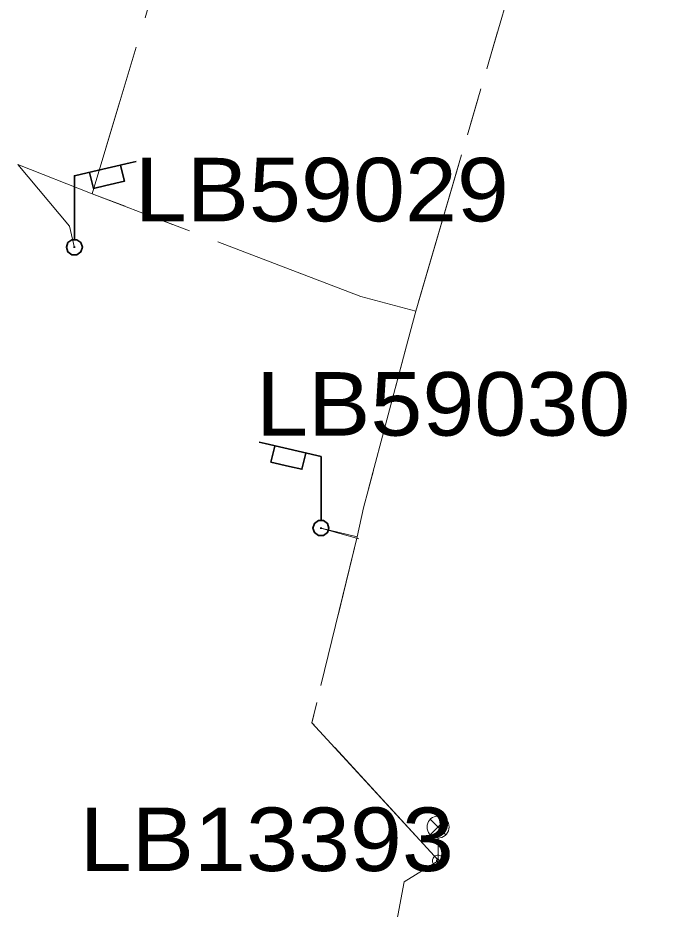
# Model space of a CAD drawing. Extents: x -688049 to -687261, y -973611 to -973038.
# Drawn here: x -687574.85 to -687553.08, y -973130.12 to -973099.72 of the extents above; entities that cross this region are included whole.
import ezdxf

# ---------------------------------------------------------------- set-up
doc = ezdxf.new("R2010")
doc.units = 0
doc.header["$LTSCALE"] = 0.87
doc.linetypes.add('LONG_DASH_SHORT_DASH', pattern=[9.9, 6, -1.2, 1.5, -1.2])
doc.layers.add('1', color=7, linetype='Continuous', lineweight=13)

msp = doc.modelspace()

# ---------------------------------------------------------------- linework, layer by layer
at = {"layer": '1', "linetype": 'LONG_DASH_SHORT_DASH'}
for p, q in [((-687561.28, -973109.72), (-687558.49, -973100.2)), ((-687561.28, -973109.72), (-687558.49, -973100.2)), ((-687571.38, -973102.61), (-687572.31, -973105.72)), ((-687571.38, -973102.61), (-687572.31, -973105.72)), ((-687571.38, -973102.61), (-687572.31, -973105.72)), ((-687572.31, -973105.72), (-687569.57, -973106.77)), ((-687572.31, -973105.72), (-687569.57, -973106.77)), ((-687572.31, -973105.72), (-687569.57, -973106.77)), ((-687564.51, -973117.12), (-687563.28, -973117.42)), ((-687564.51, -973117.12), (-687563.28, -973117.42)), ((-687564.51, -973117.12), (-687563.28, -973117.42)), ((-687564.51, -973117.12), (-687563.28, -973117.42)), ((-687564.51, -973117.12), (-687563.28, -973117.42)), ((-687564.51, -973117.12), (-687563.28, -973117.42)), ((-687564.51, -973117.12), (-687563.28, -973117.42)), ((-687564.51, -973117.12), (-687563.28, -973117.42)), ((-687563.93, -973120.09), (-687563.28, -973117.42)), ((-687563.93, -973120.09), (-687563.28, -973117.42)), ((-687563.93, -973120.09), (-687563.28, -973117.42)), ((-687563.93, -973120.09), (-687563.28, -973117.42))]:
    msp.add_line(p, q, dxfattribs=at)
at = {"layer": '1', "lineweight": 35}
for p, q in [((-687572.949, -973107.545), (-687572.895, -973107.545)), ((-687564.483, -973117.12), (-687564.537, -973117.12))]:
    msp.add_line(p, q, dxfattribs=at)
at = {"layer": '1'}
for p, q in [((-687563.22, -973117.487), (-687564.515, -973117.123)), ((-687560.785, -973127.055), (-687560.255, -973127.585)), ((-687560.785, -973127.585), (-687560.255, -973127.055)), ((-687560.52, -973128.47), (-687560.52, -973127.695))]:
    msp.add_line(p, q, dxfattribs=at)
at = {"layer": '1', "linetype": 'LONG_DASH_SHORT_DASH'}
for points in [[(-687572.31, -973105.72), (-687569.06, -973094.88), (-687566.56, -973083.47), (-687566.59, -973077.36), (-687568.45, -973067.24), (-687568.05, -973061.45)], [(-687572.31, -973105.72), (-687569.06, -973094.88), (-687566.56, -973083.47), (-687566.59, -973077.36), (-687568.45, -973067.24), (-687568.05, -973061.45)], [(-687572.31, -973105.72), (-687569.06, -973094.88), (-687566.56, -973083.47), (-687566.59, -973077.36), (-687568.45, -973067.24), (-687568.05, -973061.45)], [(-687572.31, -973105.72), (-687569.06, -973094.88), (-687566.56, -973083.47), (-687566.59, -973077.36), (-687568.45, -973067.24), (-687568.05, -973061.45)], [(-687553.08, -973087.49), (-687557.3, -973096.13), (-687561.28, -973109.72)], [(-687553.08, -973087.49), (-687557.3, -973096.13), (-687561.28, -973109.72)], [(-687553.08, -973087.49), (-687557.3, -973096.13), (-687561.28, -973109.72), (-687558.49, -973100.2)], [(-687553.08, -973087.49), (-687557.3, -973096.13), (-687561.28, -973109.72)], [(-687566.48, -973107.95), (-687563.15, -973109.23), (-687561.28, -973109.72), (-687558.49, -973100.2)], [(-687571.38, -973102.61), (-687572.31, -973105.72), (-687569.57, -973106.77)], [(-687572.31, -973105.72), (-687574.85, -973104.72), (-687573.09, -973106.82), (-687572.92, -973107.56)], [(-687572.92, -973107.56), (-687573.09, -973106.82), (-687574.85, -973104.72), (-687572.31, -973105.72)], [(-687572.92, -973107.56), (-687573.09, -973106.82), (-687574.85, -973104.72), (-687572.31, -973105.72)], [(-687572.31, -973105.72), (-687574.85, -973104.72), (-687573.09, -973106.82), (-687572.92, -973107.56)], [(-687572.92, -973107.56), (-687573.09, -973106.82), (-687574.85, -973104.72), (-687572.31, -973105.72)], [(-687572.31, -973105.72), (-687574.85, -973104.72), (-687573.09, -973106.82), (-687572.92, -973107.56)], [(-687572.31, -973105.72), (-687574.85, -973104.72), (-687573.09, -973106.82), (-687572.92, -973107.56)], [(-687572.92, -973107.56), (-687573.09, -973106.82), (-687574.85, -973104.72), (-687572.31, -973105.72)], [(-687561.28, -973109.72), (-687563.15, -973109.23), (-687572.31, -973105.72)], [(-687561.28, -973109.72), (-687563.15, -973109.23), (-687572.31, -973105.72)], [(-687561.28, -973109.72), (-687563.15, -973109.23), (-687572.31, -973105.72)], [(-687561.28, -973109.72), (-687563.15, -973109.23), (-687572.31, -973105.72)], [(-687566.48, -973107.95), (-687563.15, -973109.23), (-687561.28, -973109.72)], [(-687566.48, -973107.95), (-687563.15, -973109.23), (-687561.28, -973109.72)], [(-687566.48, -973107.95), (-687563.15, -973109.23), (-687561.28, -973109.72)], [(-687561.28, -973109.72), (-687561.55, -973110.74), (-687563.06, -973116.43), (-687563.28, -973117.42)], [(-687561.28, -973109.72), (-687561.55, -973110.74), (-687563.06, -973116.43), (-687563.28, -973117.42)], [(-687561.28, -973109.72), (-687561.55, -973110.74), (-687563.06, -973116.43), (-687563.28, -973117.42)], [(-687561.28, -973109.72), (-687561.55, -973110.74), (-687563.06, -973116.43), (-687563.28, -973117.42)], [(-687561.96, -973112.28), (-687561.55, -973110.74), (-687561.28, -973109.72)], [(-687561.96, -973112.28), (-687561.55, -973110.74), (-687561.28, -973109.72)], [(-687561.96, -973112.28), (-687561.55, -973110.74), (-687561.28, -973109.72)], [(-687561.96, -973112.28), (-687561.55, -973110.74), (-687561.28, -973109.72)], [(-687563.28, -973117.42), (-687563.06, -973116.43), (-687562.72, -973115.16)], [(-687563.28, -973117.42), (-687563.06, -973116.43), (-687562.72, -973115.16)], [(-687563.28, -973117.42), (-687563.06, -973116.43), (-687562.72, -973115.16)], [(-687563.28, -973117.42), (-687563.06, -973116.43), (-687562.72, -973115.16)], [(-687563.28, -973117.42), (-687564.82, -973123.76), (-687560.51, -973128.45)], [(-687563.28, -973117.42), (-687564.82, -973123.76), (-687560.51, -973128.45)], [(-687563.28, -973117.42), (-687564.82, -973123.76), (-687560.51, -973128.45)], [(-687563.28, -973117.42), (-687564.82, -973123.76), (-687560.51, -973128.45)], [(-687560.51, -973128.45), (-687564.82, -973123.76), (-687564.65, -973123.07)], [(-687560.51, -973128.45), (-687564.82, -973123.76), (-687564.65, -973123.07)], [(-687560.51, -973128.45), (-687564.82, -973123.76), (-687564.65, -973123.07)], [(-687560.51, -973128.45), (-687564.82, -973123.76), (-687564.65, -973123.07)]]:
    msp.add_lwpolyline(points, dxfattribs=at)
at = {"layer": '1', "lineweight": 35}
for points in [[(-687572.922, -973107.29), (-687572.835, -973107.29), (-687572.7, -973107.388), (-687572.646, -973107.545), (-687572.7, -973107.702), (-687572.835, -973107.8), (-687573.003, -973107.8), (-687573.139, -973107.702), (-687573.193, -973107.545), (-687573.139, -973107.388), (-687573.003, -973107.29), (-687572.922, -973107.29), (-687572.922, -973106.602), (-687572.922, -973105.914), (-687572.922, -973105.226), (-687572.922, -973105.107), (-687572.288, -973104.96), (-687571.654, -973104.814), (-687571.02, -973104.668), (-687570.809, -973104.619)], [(-687571.351, -973104.754), (-687571.215, -973105.296), (-687571.849, -973105.443), (-687572.272, -973105.54), (-687572.407, -973104.998)], [(-687564.51, -973116.865), (-687564.597, -973116.865), (-687564.732, -973116.963), (-687564.786, -973117.12), (-687564.732, -973117.277), (-687564.597, -973117.375), (-687564.429, -973117.375), (-687564.293, -973117.277), (-687564.239, -973117.12), (-687564.293, -973116.963), (-687564.429, -973116.865), (-687564.51, -973116.865), (-687564.51, -973116.177), (-687564.51, -973115.489), (-687564.51, -973114.801), (-687564.51, -973114.682), (-687565.144, -973114.535), (-687565.778, -973114.389), (-687566.412, -973114.243), (-687566.623, -973114.194)], [(-687566.081, -973114.329), (-687566.217, -973114.871), (-687565.583, -973115.018), (-687565.16, -973115.115), (-687565.025, -973114.573)]]:
    msp.add_lwpolyline(points, dxfattribs=at)
at = {"layer": '1'}
for points in [[(-687560.145, -973127.32), (-687560.151, -973127.255), (-687560.168, -973127.192), (-687560.195, -973127.133), (-687560.233, -973127.079), (-687560.279, -973127.033), (-687560.332, -973126.995), (-687560.392, -973126.968), (-687560.455, -973126.951), (-687560.52, -973126.945), (-687560.585, -973126.951), (-687560.648, -973126.968), (-687560.708, -973126.995), (-687560.761, -973127.033), (-687560.807, -973127.079), (-687560.845, -973127.133), (-687560.872, -973127.192), (-687560.889, -973127.255), (-687560.895, -973127.32), (-687560.889, -973127.385), (-687560.872, -973127.448), (-687560.845, -973127.508), (-687560.807, -973127.561), (-687560.761, -973127.607), (-687560.708, -973127.645), (-687560.648, -973127.672), (-687560.585, -973127.689), (-687560.52, -973127.695), (-687560.455, -973127.689), (-687560.392, -973127.672), (-687560.332, -973127.645), (-687560.279, -973127.607), (-687560.233, -973127.561), (-687560.195, -973127.508), (-687560.168, -973127.448), (-687560.151, -973127.385)], [(-687560.33, -973128.47), (-687560.333, -973128.437), (-687560.341, -973128.405), (-687560.355, -973128.375), (-687560.374, -973128.348), (-687560.398, -973128.324), (-687560.425, -973128.305), (-687560.455, -973128.291), (-687560.487, -973128.283), (-687560.52, -973128.28), (-687560.553, -973128.283), (-687560.585, -973128.291), (-687560.615, -973128.305), (-687560.642, -973128.324), (-687560.666, -973128.348), (-687560.685, -973128.375), (-687560.699, -973128.405), (-687560.707, -973128.437), (-687560.71, -973128.47), (-687560.707, -973128.503), (-687560.699, -973128.535), (-687560.685, -973128.565), (-687560.666, -973128.592), (-687560.642, -973128.616), (-687560.615, -973128.635), (-687560.585, -973128.649), (-687560.553, -973128.657), (-687560.52, -973128.66), (-687560.487, -973128.657), (-687560.455, -973128.649), (-687560.425, -973128.635), (-687560.398, -973128.616), (-687560.374, -973128.592), (-687560.355, -973128.565), (-687560.341, -973128.535), (-687560.333, -973128.503)], [(-687560.47, -973128.47), (-687560.471, -973128.461), (-687560.473, -973128.453), (-687560.477, -973128.445), (-687560.482, -973128.438), (-687560.488, -973128.432), (-687560.495, -973128.427), (-687560.503, -973128.423), (-687560.511, -973128.421), (-687560.52, -973128.42), (-687560.529, -973128.421), (-687560.537, -973128.423), (-687560.545, -973128.427), (-687560.552, -973128.432), (-687560.558, -973128.438), (-687560.563, -973128.445), (-687560.567, -973128.453), (-687560.569, -973128.461), (-687560.57, -973128.47), (-687560.569, -973128.479), (-687560.567, -973128.487), (-687560.563, -973128.495), (-687560.558, -973128.502), (-687560.552, -973128.508), (-687560.545, -973128.513), (-687560.537, -973128.517), (-687560.529, -973128.519), (-687560.52, -973128.52), (-687560.511, -973128.519), (-687560.503, -973128.517), (-687560.495, -973128.513), (-687560.488, -973128.508), (-687560.482, -973128.502), (-687560.477, -973128.495), (-687560.473, -973128.487), (-687560.471, -973128.479)]]:
    msp.add_lwpolyline(points, close=True, dxfattribs=at)
msp.add_lwpolyline([(-687568.06, -973166.7), (-687568.547, -973165.841), (-687561.677, -973129.186), (-687560.52, -973128.47)], dxfattribs=at)

# ---------------------------------------------------------------- texts
at = {"layer": '1', "width": 1.1}
for s, p in [('LB59029', (-687570.865, -973106.662)), ('LB59030', (-687566.724, -973113.97)), ('LB13393', (-687572.74, -973128.82))]:
    msp.add_text(s, height=2.167, dxfattribs=at).set_placement(p)

doc.saveas('drawing.dxf')
